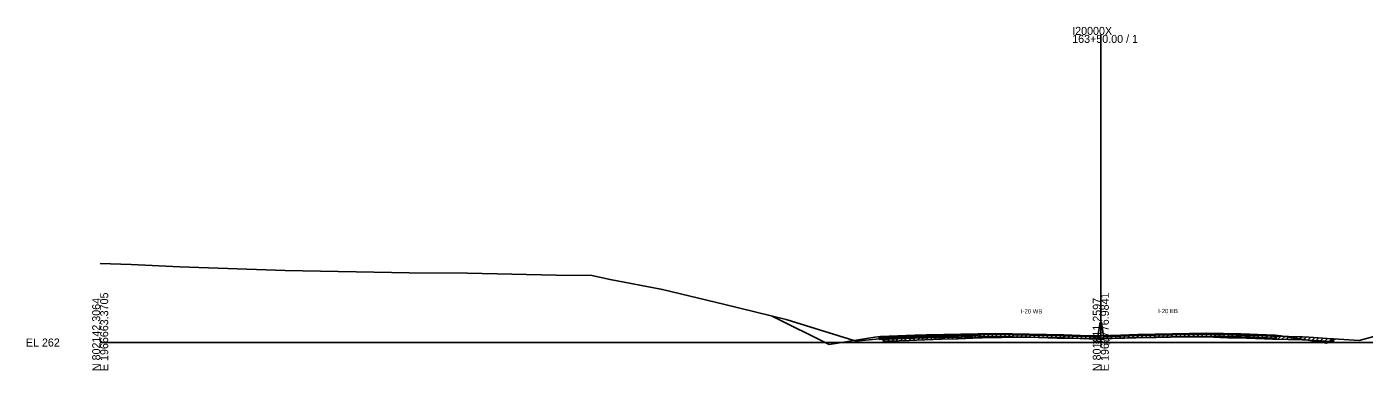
# Model space of a CAD drawing. Extents: x -4026 to 9638, y -10 to 19609.
# Drawn here: x 3974.3 to 4442.2, y 4990.3 to 5110.4 of the extents above; entities that cross this region are included whole.
import ezdxf

# ---------------------------------------------------------------- set-up
doc = ezdxf.new("R2010")
doc.units = 0
for name, color, linetype in [('Default', 7, 'Continuous'), ('RD_GPK_XS_Cell', 7, 'Continuous'), ('RD_TX_Misc1', 7, 'Continuous'), ('RD_XS_Base', 7, 'Continuous'), ('RD_XS_ExGround', 7, 'Continuous'), ('RD_XS_ExPaveRet', 7, 'Continuous'), ('RD_XS_Greenside', 7, 'Continuous'), ('RD_XS_MedBWall', 7, 'Continuous'), ('RD_XS_Pave', 7, 'Continuous'), ('RD_XS_PaveOvlay', 7, 'Continuous'), ('RD_XS_TieSlope', 7, 'Continuous'), ('RD_XS_TX_Elev_EX', 7, 'Continuous')]:
    doc.layers.add(name, color=color, linetype=linetype)

msp = doc.modelspace()

# ---------------------------------------------------------------- linework, layer by layer
at = {"layer": 'RD_GPK_XS_Cell'}
for p, q in [((4350, 5000), (4350, 5107.57)), ((4000, 5000), (4350, 5000)), ((4350, 5000), (4700, 5000))]:
    msp.add_line(p, q, dxfattribs=at)
at = {"layer": 'RD_XS_Base'}
for points in [[(4272.5, 5001.74), (4273, 5001.76), (4285, 5002.23)], [(4272.5, 5001.07), (4272.5, 5001.74)], [(4285, 5001.56), (4272.5, 5001.07)], [(4285, 5002.23), (4289, 5002.33)], [(4285, 5001.56), (4285, 5002.23)], [(4289, 5001.66), (4285, 5001.56)], [(4337, 5002.33), (4313, 5002.82), (4289, 5002.33)], [(4289, 5002.33), (4289, 5001.66)], [(4289, 5001.66), (4313, 5002.15), (4337, 5001.66)], [(4337, 5001.66), (4337, 5002.33)], [(4349, 5001.86), (4337, 5002.33)], [(4337, 5001.66), (4349, 5001.19)], [(4349, 5001.19), (4349, 5001.86)], [(4351, 5001.98), (4363, 5002.46)], [(4351, 5001.31), (4351, 5001.98)], [(4363, 5001.79), (4351, 5001.31)], [(4363, 5002.46), (4387, 5002.94), (4399, 5002.7)], [(4363, 5001.79), (4363, 5002.46)], [(4399, 5002.03), (4387, 5002.27), (4363, 5001.79)], [(4399, 5002.7), (4399, 5002.7), (4399, 5002.03), (4399, 5002.03)], [(4399, 5002.03), (4399, 5002.7)], [(4411.5, 5002.2), (4411, 5002.22), (4399, 5002.7)], [(4399, 5002.03), (4411.5, 5001.53)], [(4411.5, 5001.53), (4411.5, 5002.2)]]:
    msp.add_lwpolyline(points, dxfattribs=at)
at = {"layer": 'RD_XS_ExGround'}
msp.add_lwpolyline([(4000, 5027.58), (4010.83, 5027.24), (4027.87, 5026.52), (4064.74, 5025.14), (4108.07, 5024.41), (4128.5, 5024.23), (4159.47, 5023.57), (4171.92, 5023.41), (4178.37, 5022.01), (4196.63, 5018.49), (4218.48, 5013.27), (4239.89, 5008.05), (4261.74, 5001.29), (4264.43, 5000.52), (4266.54, 5000.73), (4273.88, 5001.44), (4276.02, 5001.5), (4282.92, 5001.73), (4285.51, 5001.83), (4294.33, 5002.16), (4300.09, 5002.34), (4305.25, 5002.51), (4307.22, 5002.6), (4308.46, 5002.66), (4315.31, 5002.79), (4320.38, 5002.89), (4328.23, 5002.72), (4331.44, 5002.64), (4334.77, 5002.57), (4342.77, 5002.43), (4346.96, 5002.32), (4347.85, 5002.3), (4348.57, 5002.32), (4350, 5002.35), (4353.13, 5002.43), (4355.72, 5002.5), (4358.31, 5002.57), (4362.33, 5002.63), (4369.31, 5002.73), (4379.56, 5002.97), (4380.84, 5003), (4389.39, 5002.83), (4391.73, 5002.78), (4394.48, 5002.69), (4400.97, 5002.51), (4407.3, 5002.32), (4410.08, 5002.22), (4415.71, 5002.09), (4419.42, 5002), (4420.55, 5001.95), (4422.73, 5001.84), (4430.85, 5001.34), (4431.4, 5001.3), (4440.38, 5000.65), (4483.83, 5012.55)], dxfattribs=at)
at = {"layer": 'RD_XS_ExPaveRet'}
for p, q in [((4273.88, 5000.44), (4274.91, 5001.47)), ((4273.88, 5000.44), (4273.88, 5001.44)), ((4275.38, 5000.48), (4276.41, 5001.51)), ((4276.88, 5000.53), (4277.91, 5001.56)), ((4278.38, 5000.58), (4279.41, 5001.61)), ((4279.88, 5000.63), (4280.91, 5001.66)), ((4281.38, 5000.68), (4282.41, 5001.71)), ((4282.88, 5000.73), (4283.92, 5001.77)), ((4284.38, 5000.78), (4285.42, 5001.83)), ((4285.88, 5000.84), (4286.92, 5001.88)), ((4287.38, 5000.9), (4288.42, 5001.94)), ((4288.88, 5000.95), (4289.92, 5001.99)), ((4290.38, 5001.01), (4291.42, 5002.05)), ((4291.88, 5001.07), (4292.92, 5002.11)), ((4293.38, 5001.12), (4294.42, 5002.16)), ((4294.33, 5001.16), (4300.09, 5001.34)), ((4294.88, 5001.18), (4295.91, 5002.21)), ((4296.38, 5001.22), (4297.41, 5002.26)), ((4297.88, 5001.27), (4298.91, 5002.3)), ((4299.38, 5001.32), (4300.41, 5002.35)), ((4300.09, 5001.34), (4305.25, 5001.51)), ((4300.88, 5001.37), (4301.91, 5002.4)), ((4302.38, 5001.42), (4303.41, 5002.45)), ((4303.88, 5001.47), (4304.91, 5002.5)), ((4305.25, 5001.51), (4307.22, 5001.6)), ((4305.38, 5001.52), (4306.42, 5002.56)), ((4306.88, 5001.58), (4307.93, 5002.63)), ((4307.22, 5001.6), (4308.46, 5001.66)), ((4308.38, 5001.66), (4309.4, 5002.68)), ((4308.46, 5001.66), (4315.31, 5001.79)), ((4309.88, 5001.69), (4310.9, 5002.7)), ((4311.38, 5001.71), (4312.4, 5002.73)), ((4312.88, 5001.74), (4313.9, 5002.76)), ((4314.38, 5001.77), (4315.4, 5002.79)), ((4315.31, 5001.79), (4320.38, 5001.89)), ((4315.88, 5001.8), (4316.9, 5002.82)), ((4317.38, 5001.83), (4318.4, 5002.85)), ((4318.88, 5001.86), (4319.9, 5002.88)), ((4320.38, 5001.89), (4321.36, 5002.87)), ((4320.38, 5001.89), (4328.23, 5001.72)), ((4321.88, 5001.86), (4322.86, 5002.84)), ((4323.38, 5001.82), (4324.36, 5002.8)), ((4324.88, 5001.79), (4325.86, 5002.77)), ((4326.38, 5001.76), (4327.36, 5002.74)), ((4327.88, 5001.72), (4328.86, 5002.7)), ((4328.23, 5001.72), (4331.44, 5001.64)), ((4329.38, 5001.69), (4330.35, 5002.66)), ((4330.88, 5001.65), (4331.86, 5002.63)), ((4331.44, 5001.64), (4334.77, 5001.57)), ((4332.38, 5001.62), (4333.36, 5002.6)), ((4333.88, 5001.59), (4334.86, 5002.57)), ((4334.77, 5001.57), (4342.77, 5001.43)), ((4335.38, 5001.56), (4336.36, 5002.55)), ((4336.88, 5001.54), (4337.86, 5002.52)), ((4338.38, 5001.51), (4339.36, 5002.49)), ((4339.88, 5001.48), (4340.86, 5002.46)), ((4341.38, 5001.46), (4342.36, 5002.44)), ((4342.77, 5001.43), (4346.96, 5001.32)), ((4342.88, 5001.43), (4343.85, 5002.4)), ((4344.38, 5001.39), (4345.35, 5002.37)), ((4345.88, 5001.35), (4346.85, 5002.33)), ((4346.96, 5001.32), (4347.85, 5001.3)), ((4347.38, 5001.31), (4348.38, 5002.31)), ((4347.85, 5001.3), (4348.57, 5001.32)), ((4348.57, 5001.32), (4350, 5001.35)), ((4348.88, 5001.33), (4349.9, 5002.35)), ((4350, 5001.35), (4353.13, 5001.43)), ((4350.38, 5001.36), (4351.4, 5002.39)), ((4351.88, 5001.4), (4352.9, 5002.43)), ((4353.13, 5001.43), (4355.72, 5001.5)), ((4353.38, 5001.44), (4354.41, 5002.47)), ((4354.88, 5001.48), (4355.91, 5002.51)), ((4355.72, 5001.5), (4358.31, 5001.57)), ((4356.38, 5001.52), (4357.41, 5002.55)), ((4357.88, 5001.56), (4358.9, 5002.58)), ((4358.31, 5001.57), (4362.33, 5001.63)), ((4359.38, 5001.59), (4360.39, 5002.6)), ((4360.88, 5001.61), (4361.89, 5002.62)), ((4362.33, 5001.63), (4369.31, 5001.73)), ((4362.38, 5001.63), (4363.39, 5002.65)), ((4363.88, 5001.65), (4364.89, 5002.67)), ((4365.38, 5001.67), (4366.39, 5002.69)), ((4366.88, 5001.7), (4367.89, 5002.71)), ((4368.38, 5001.72), (4369.39, 5002.73)), ((4369.31, 5001.73), (4379.56, 5001.97)), ((4369.88, 5001.75), (4370.9, 5002.77)), ((4371.38, 5001.78), (4372.4, 5002.8)), ((4372.88, 5001.82), (4373.9, 5002.84)), ((4374.38, 5001.85), (4375.4, 5002.87)), ((4375.88, 5001.89), (4376.9, 5002.91)), ((4377.38, 5001.92), (4378.4, 5002.95)), ((4378.88, 5001.96), (4379.9, 5002.98)), ((4379.56, 5001.97), (4380.84, 5002)), ((4380.38, 5001.99), (4381.38, 5002.99)), ((4380.84, 5002), (4389.39, 5001.83)), ((4381.88, 5001.98), (4382.86, 5002.96)), ((4383.38, 5001.95), (4384.36, 5002.93)), ((4384.88, 5001.92), (4385.86, 5002.9)), ((4386.38, 5001.89), (4387.36, 5002.87)), ((4387.88, 5001.86), (4388.86, 5002.84)), ((4389.38, 5001.83), (4390.36, 5002.81)), ((4389.39, 5001.83), (4391.73, 5001.78)), ((4390.88, 5001.8), (4391.86, 5002.78)), ((4391.73, 5001.78), (4394.48, 5001.69)), ((4392.38, 5001.76), (4393.35, 5002.73)), ((4393.88, 5001.71), (4394.85, 5002.68)), ((4394.48, 5001.69), (4400.97, 5001.51)), ((4395.38, 5001.67), (4396.35, 5002.64)), ((4396.88, 5001.62), (4397.85, 5002.6)), ((4398.38, 5001.58), (4399.35, 5002.55)), ((4399.88, 5001.54), (4400.85, 5002.51)), ((4400.97, 5001.51), (4407.3, 5001.32)), ((4401.38, 5001.49), (4402.35, 5002.47)), ((4402.88, 5001.45), (4403.85, 5002.42)), ((4404.38, 5001.41), (4405.35, 5002.38)), ((4405.88, 5001.36), (4406.85, 5002.33)), ((4407.3, 5001.32), (4410.08, 5001.22)), ((4407.38, 5001.32), (4408.34, 5002.28)), ((4408.88, 5001.26), (4409.84, 5002.23)), ((4410.38, 5001.21), (4411.36, 5002.19)), ((4411.88, 5001.18), (4412.86, 5002.16)), ((4413.38, 5001.14), (4414.36, 5002.12)), ((4414.88, 5001.11), (4415.86, 5002.09)), ((4416.38, 5001.07), (4417.36, 5002.05)), ((4417.88, 5001.04), (4418.86, 5002.02)), ((4419.38, 5001), (4420.33, 5001.96)), ((4420.88, 5000.93), (4421.83, 5001.89)), ((4422.38, 5000.86), (4423.32, 5001.81)), ((4423.88, 5000.77), (4424.82, 5001.71)), ((4425.38, 5000.68), (4426.32, 5001.62)), ((4426.88, 5000.59), (4427.82, 5001.53)), ((4428.38, 5000.49), (4429.32, 5001.43)), ((4429.88, 5000.4), (4430.82, 5001.34)), ((4431.4, 5001.3), (4431.4, 5000.3)), ((4273.88, 5000.44), (4276.02, 5000.5)), ((4276.02, 5000.5), (4282.92, 5000.73)), ((4282.92, 5000.73), (4285.51, 5000.83)), ((4285.51, 5000.83), (4294.33, 5001.16)), ((4410.08, 5001.22), (4415.71, 5001.09)), ((4415.71, 5001.09), (4419.42, 5001)), ((4419.42, 5001), (4420.55, 5000.95)), ((4420.55, 5000.95), (4422.73, 5000.84)), ((4422.73, 5000.84), (4430.85, 5000.34)), ((4430.85, 5000.34), (4431.4, 5000.3))]:
    msp.add_line(p, q, dxfattribs=at)
at = {"layer": 'RD_XS_Greenside'}
for points in [[(4271, 5001.93), (4255, 4999.26)], [(4273, 5002.09), (4271, 5001.93)], [(4411, 5002.55), (4413, 5002.39)], [(4413, 5002.39), (4429, 4999.72)]]:
    msp.add_lwpolyline(points, dxfattribs=at)
at = {"layer": 'RD_XS_MedBWall'}
for points in [[(4349, 5002.19), (4349.75, 5006.98), (4350.25, 5006.98), (4351, 5002.31)], [(4349, 5001.19), (4349, 5002.19)], [(4351, 5002.31), (4351, 5001.19)], [(4351, 5001.19), (4349, 5001.19)]]:
    msp.add_lwpolyline(points, dxfattribs=at)
at = {"layer": 'RD_XS_Pave'}
for points in [[(4273, 5001.92), (4285, 5002.4)], [(4285, 5002.23), (4273, 5001.76)], [(4273, 5001.76), (4273, 5001.92)], [(4285, 5002.4), (4289, 5002.5)], [(4285, 5002.23), (4285, 5002.4)], [(4289, 5002.33), (4285, 5002.23)], [(4289, 5002.5), (4313, 5002.98), (4337, 5002.5)], [(4337, 5002.33), (4313, 5002.82), (4289, 5002.33)], [(4289, 5002.5), (4289, 5002.33)], [(4337, 5002.5), (4349, 5002.03)], [(4337, 5002.33), (4337, 5002.5)], [(4349, 5001.86), (4337, 5002.33)], [(4349, 5002.03), (4349, 5001.86)], [(4363, 5002.63), (4351, 5002.15)], [(4351, 5001.98), (4363, 5002.46)], [(4351, 5002.15), (4351, 5001.98)], [(4399, 5002.87), (4387, 5003.11), (4363, 5002.63)], [(4363, 5002.46), (4387, 5002.94), (4399, 5002.7)], [(4363, 5002.63), (4363, 5002.46)], [(4399, 5002.87), (4399, 5002.87), (4399, 5002.7), (4399, 5002.7)], [(4399, 5002.7), (4399, 5002.87)], [(4411, 5002.39), (4399, 5002.87)], [(4399, 5002.7), (4411, 5002.22)], [(4411, 5002.22), (4411, 5002.39)]]:
    msp.add_lwpolyline(points, dxfattribs=at)
at = {"layer": 'RD_XS_PaveOvlay'}
for points in [[(4273, 5002.09), (4285, 5002.57)], [(4285, 5002.4), (4273, 5001.92)], [(4273, 5001.92), (4273, 5002.09)], [(4289, 5002.67), (4285, 5002.57)], [(4285, 5002.57), (4285, 5002.4)], [(4285, 5002.4), (4289, 5002.5)], [(4289, 5002.67), (4313, 5003.15), (4337, 5002.67)], [(4337, 5002.5), (4313, 5002.98), (4289, 5002.5)], [(4289, 5002.5), (4289, 5002.67)], [(4337, 5002.67), (4337, 5002.5)], [(4337, 5002.67), (4349, 5002.19)], [(4349, 5002.03), (4337, 5002.5)], [(4349, 5002.19), (4349, 5002.03)], [(4363, 5002.79), (4351, 5002.31)], [(4351, 5002.15), (4363, 5002.63)], [(4351, 5002.31), (4351, 5002.15)], [(4399, 5003.03), (4387, 5003.27), (4363, 5002.79)], [(4363, 5002.63), (4387, 5003.11), (4399, 5002.87)], [(4363, 5002.79), (4363, 5002.63)], [(4399, 5002.87), (4399, 5003.03)], [(4399, 5003.03), (4399, 5003.03), (4399, 5002.87), (4399, 5002.87)], [(4399, 5003.03), (4411, 5002.55)], [(4411, 5002.39), (4399, 5002.87)], [(4411, 5002.55), (4411, 5002.39)]]:
    msp.add_lwpolyline(points, dxfattribs=at)
at = {"layer": 'RD_XS_TieSlope'}
for points in [[(4255, 4999.26), (4235.1, 5009.21)], [(4429, 4999.72), (4432.07, 5001.25)]]:
    msp.add_lwpolyline(points, dxfattribs=at)

# ---------------------------------------------------------------- texts
at = {"layer": 'Default'}
msp.add_text('-', height=0.0001, dxfattribs=at).set_placement((4000, 5000))
at = {"layer": 'RD_GPK_XS_Cell'}
for s, p in [('I20000X', (4340, 5107.57)), ('163+50.00 / 1', (4340, 5104.77)), ('EL 262', (3974, 4998.6))]:
    msp.add_text(s, height=2.8, dxfattribs=at).set_placement(p)
for s, p in [('N 802142.3064', (4000, 4990)), ('E 1966663.3705', (4002.8, 4990)), ('N 801811.2597', (4350, 4990)), ('E 1966776.9841', (4352.8, 4990))]:
    msp.add_text(s, height=2.8, rotation=90, dxfattribs=at).set_placement(p)
at = {"layer": 'RD_TX_Misc1'}
for s, p in [('I-20 WB', (4322.06, 5010.15)), ('I-20 EB', (4370.06, 5010.27))]:
    msp.add_text(s, height=1.5, dxfattribs=at).set_placement(p)
at = {"layer": 'RD_XS_TX_Elev_EX'}
msp.add_text('264.35', height=1.5, dxfattribs=at).set_placement((4347.1, 4999.35))

doc.saveas('drawing.dxf')
